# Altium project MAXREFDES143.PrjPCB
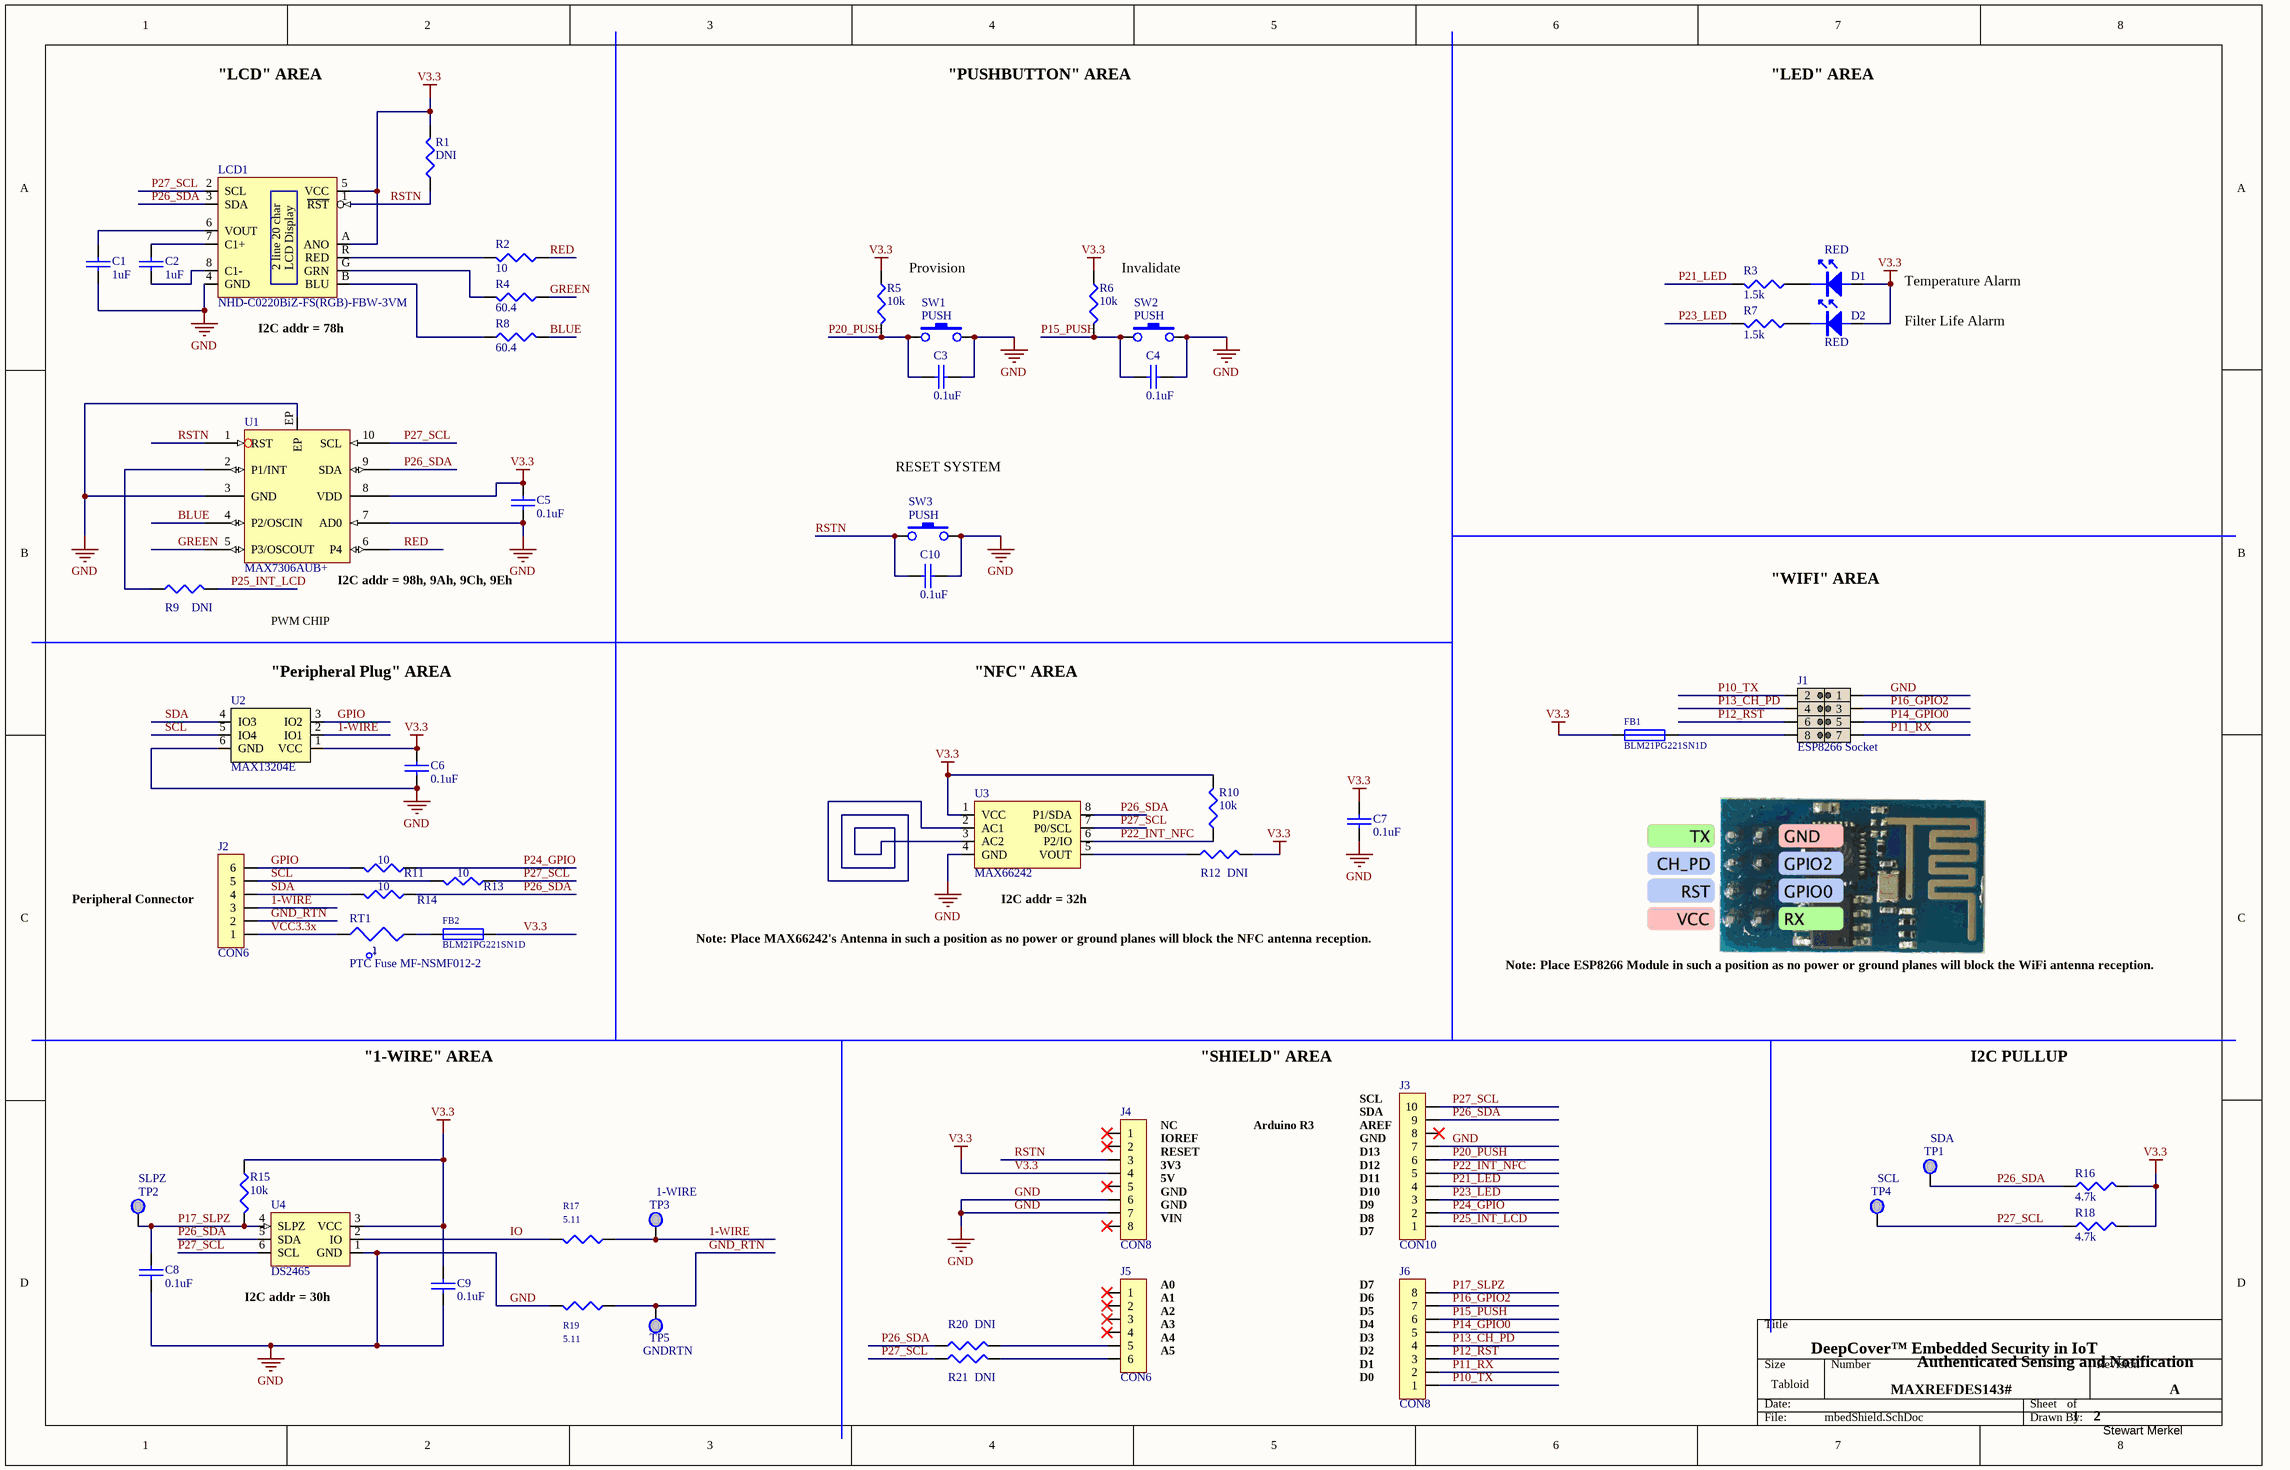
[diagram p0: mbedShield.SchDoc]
2 sheets, 65 parts. Net scope: flat (ports and power ports of the same name join across sheets).
Board file: MAXREFDES143.PcbDoc
Sheets:
  mbedShield.SchDoc
  ProtectedSensorNode.SchDoc

## Sheet mbedShield.SchDoc
size Tabloid; SheetNumber: 1; SheetTotal: 1; PageSetup: Record=PageOptions|CenterHorizontal=True|CenterVertical=True|PrintScale=0.95|XCorrection=1.00|YCorrection=1.00|PrintKind=1|BorderSize=5000000|LeftOffset=0|BottomOffset=0|Orientation=2|PaperLength=4318|PaperWidth=2794|Scale=100|PaperSource=7|PrintQuality=600|MediaType=1|DitherType=10|PaperKind=11x17|PrintScaleMode=1

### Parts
C1  1uF  [CAP0603-3D]
C2  1uF  [CAP0603-3D]
C3  0.1uF  [CAP0603-3D]
C4  0.1uF  [CAP0603-3D]
C5  0.1uF  [CAP0603-3D]
C6  0.1uF  [CAP0603-3D]
C7  0.1uF  [CAP0603-3D]
C8  0.1uF  [CAP0603-3D]
C9  0.1uF  [CAP0603-3D]
C10  0.1uF  [CAP0603-3D]
D1  RED  [0603LED-3DRED]
D2  RED  [0603LED-3DRED]
FB1  BLM21PG221SN1D  [0805FB-3D]
FB2  BLM21PG221SN1D  [0805FB-3D]
J1  ESP8266 Socket  [DIH4X2]
J2  CON6  [SIP6]
J3  CON10  [SIP10-FEM-3D]
J4  CON8  [SIP8-FEM-3D]
J5  CON6  [SIP6-FEM-3D]
J6  CON8  [SIP8-FEM-3D]
LCD1  NHD-C0220BiZ-FS(RGB)-FBW-3VM  [NHD RGB LCD 1]
R1  DNI  [0603-3D]  (no BOM)
R2  10  [0603-3D]
R3  1.5k  [0603-3D]
R4  60.4  [0603-3D]
R5  10k  [0603-3D]
R6  10k  [0603-3D]
R7  1.5k  [0603-3D]
R8  60.4  [0603-3D]
R9  DNI  [0603-3D]  (no BOM)
R10  10k  [0603-3D]
R11  10  [0603-3D]
R12  DNI  [0603-3D]  (no BOM)
R13  10  [0603-3D]
R14  10  [0603-3D]
R15  10k  [0603-3D]
R16  4.7k  [0603-3D]
R17  5.11  [0603-3D]
R18  4.7k  [0603-3D]
R19  5.11  [0603-3D]
R20  DNI  [0603-3D]  (no BOM)
R21  DNI  [0603-3D]  (no BOM)
RT1  PTC Fuse MF-NSMF012-2  [1206POLYFUSE-3D]
SW1  PUSH  [RESET11-3D]
SW2  PUSH  [RESET11-3D]
SW3  PUSH  [RESET11-3D]
TP1  SDA  [TP]  (no BOM)
TP2  SLPZ  [TP]  (no BOM)
TP3  1-WIRE  [TP]  (no BOM)
TP4  SCL  [TP]  (no BOM)
TP5  GNDRTN  [TP]  (no BOM)
U1  MAX7306AUB+  [uMax10]
U2  MAX13204E  [TDFN6 2MM .65]
U3  MAX66242  [SO-8-3D]
U4  DS2465  [SOP6]

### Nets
GND: C1.2 C3.2 C4.2 C5.2 C6.2 C7.2 C8.1 C9.1 C10.2 J1.1 J3.7 J4.6 J4.7 LCD1.4(GND) R19.2 SW1.2 SW2.2 SW3.2 U1.3(GND) U1.7(AD0) U1.EP U2.6(GND) U3.4(GND) U4.1(GND)
V3.3: C5.1 C6.1 C7.1 C9.2 D1.2 D2.2 FB1.1 FB2.2 J4.4 LCD1.5(VCC) LCD1.A(ANO) R1.2 R5.2 R6.2 R10.2 R12.2 R15.2 R16.2 R18.2 U1.8(VDD) U2.1(VCC) U3.1(VCC) U4.3(VCC)
1-WIRE: J2.3 R17.1 TP3.1 U2.2(IO1)
BLUE: R8.2 U1.4(P2/OSCIN)
GND_RTN: J2.2 R19.1 TP5.1
GPIO: J2.6 R11.2 U2.3(IO2)
GREEN: R4.1 U1.5(P3/OSCOUT)
IO: R17.2 U4.2(IO)
P10_TX: J1.2 J6.1
P11_RX: J1.7 J6.2
P12_RST: J1.6 J6.3
P13_CH_PD: J1.4 J6.4
P14_GPIO0: J1.5 J6.5
P15_PUSH: C4.1 J6.6 R6.1 SW2.1
P16_GPIO2: J1.3 J6.7
P17_SLPZ: C8.2 J6.8 R15.1 TP2.1 U4.4(SLPZ)
P20_PUSH: C3.1 J3.6 R5.1 SW1.1
P21_LED: J3.4 R3.1
P22_INT_NFC: J3.5 R10.1 U3.6(P2/IO)
P23_LED: J3.3 R7.1
P24_GPIO: J3.2 R11.1
P25_INT_LCD: J3.1 R9.2
P26_SDA: J3.9 LCD1.3(SDA) R14.1 R16.1 R20.1 TP1.1 U1.9(SDA) U3.8(P1/SDA) U4.5(SDA)
P27_SCL: J3.10 LCD1.2(SCL) R13.1 R18.1 R21.1 TP4.1 U1.10(SCL) U3.7(P0/SCL) U4.6(SCL)
RED: R2.1 U1.6(P4)
RSTN: C10.1 J4.3 LCD1.1(~{RST}) R1.1 SW3.1 U1.1(RST)
SCL: J2.5 R13.2 U2.5(IO4)
SDA: J2.4 R14.2 U2.4(IO3)
VCC3.3x: J2.1 RT1.2
NetC1_1: C1.1 LCD1.6(VOUT)
NetC2_1: C2.1 LCD1.7(C1+)
NetC2_2: C2.2 LCD1.8(C1-)
NetD1_1: D1.1 R3.2
NetD2_1: D2.1 R7.2
NetFB1_2: FB1.2 J1.8
NetFB2_1: FB2.1 RT1.1
NetJ5_5: J5.5 R20.2
NetJ5_6: J5.6 R21.2
NetLCD1_B: LCD1.B(BLU) R8.1
NetLCD1_G: LCD1.G(GRN) R4.2
NetLCD1_R: LCD1.R(RED) R2.2
NetR9_1: R9.1 U1.2(P1/INT)
NetR12_1: R12.1 U3.5(VOUT)
NetU3_2: U3.2(AC1) U3.3(AC2)

Not connected (* = marked no-connect by the designer): J3 8*; J4 1* 2* 5* 8*; J5 1* 2* 3* 4*

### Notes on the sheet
- "LCD" AREA
- "PUSHBUTTON" AREA
- "LED" AREA
- (near R5) Provision
- (near R6) Invalidate
- Temperature Alarm
- (near LCD1) I2C addr = 78h
- Filter Life Alarm
- RESET SYSTEM
- PWM CHIP
- (near U1) I2C addr = 98h, 9Ah, 9Ch, 9Eh
- "WIFI" AREA
- (near U2) "Peripheral Plug" AREA
- "NFC" AREA
- (near J2) Peripheral Connector
- Note: Place MAX66242's Antenna in such a position as no power or ground planes will block the NFC antenna reception.
- (near U3) I2C addr = 32h
- Note: Place ESP8266 Module in such a position as no power or ground planes will block the WiFi antenna reception.
- "1-WIRE" AREA
- "SHIELD" AREA
- I2C PULLUP
- (near J4) NC
- (near J4) IOREF
- (near J4) RESET
- Arduino R3
- (near J3) SCL
- (near J3) SDA
- (near J3) AREF
- (near J3) D13
- (near J3) GND
- (near J4) 3V3
- (near J4) 5V
- (near J4) GND
- (near J4) VIN
- (near J3) D12
- (near J3) D11
- (near J3) D10
- D9
- D8
- (near J5) A0
- D7
- (near U4) I2C addr = 30h
- (near J5) A1
- (near J5) A2
- (near J5) A3
- (near J5) A4
- (near J5) A5
- D5
- D4
- D3
- D2
- D6
- DeepCover™ Embedded Security in IoT
- D1
- D0
- MAXREFDES143#
- Authenticated Sensing and Notification
- 1
- 2
- A
- Stewart Merkel

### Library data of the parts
C1 C2 = CAP: CAP CER 1UF 10V 10% X7R 0603; Manufacture Name: Taiyo Yuden; Part Number: LMK107B7105KA-T; Vendor Part Number: 587-1242-2-ND; Vendor: Digikey
C3-C5 C10 = CAP: CAP CER 0.1UF 16V 10% X7R 0603; Manufacture Name: Samsung Electro-Mechanics America, Inc; Part Number: CL10B104KO8NNNC; Vendor Part Number: 1276-1005-2-ND; Vendor: Digikey
C6-C9 = CAP: CAP CER 0.1UF 16V 10% X7R 0603; Manufacture Name: Samsung Electro-Mechanics America, Inc; Part Number: CL10B104KO8NNNC; Internal Part Number: EC2256
D1 D2 = LED: LED RED RECT CLEAR 0603; Manufacture Name: Lite-On Inc; Part Number: LTST-C193KRKT-5A; Vendor Part Number: 160-1830-1-ND; Vendor: Digikey
FB1 FB2 = FUSE1: Ferrite Chip; Manufacture Name: Murata Electronics North America; Vendor Part Number: 490-1054-1-ND; Vendor: Digikey
J1 = JUMPBLOCK 4: 8 Position Header Socket 0.100" (2.54mm) Through Hole; Manufacture Name: Sullins Connector Solutions; Part Number: PPTC042LFBN-RC; Vendor Part Number: S7072-ND; Vendor: Digikey
J2 = CON6: 6 Position Header Socket 0.100" (2.54mm) Through Hole, Right Angle; Manufacture Name: Sullins Connector Solutions; Part Number: PPPC061LGBN-RC; Vendor Part Number: S5481-ND; Vendor: Digikey
J3 = CON10: 10 Position Header 0.100" (2.54mm) Through Hole; Manufacture Name: Sullins Connector Solutions; Part Number: PREC040SAAN-RC; Vendor Part Number: S1012EC-40-ND; Vendor: Digikey
J4 J6 = CON8: 8 Position Header 0.100" (2.54mm) Through Hole; Manufacture Name: Sullins Connector Solutions; Part Number: PREC040SAAN-RC; Vendor Part Number: S1012EC-40-ND; Vendor: Digikey
J5 = CON6: 6 Position Header 0.100" (2.54mm) Through Hole; Manufacture Name: Sullins Connector Solutions; Part Number: PREC040SAAN-RC; Vendor Part Number: S1012EC-40-ND; Vendor: Digikey
LCD1 = NHD C0220BiZ-FS(RGB)-FBW-3VM: LCD DISPLAY RGB LED BKLT 20 X 2; Manufacture Name: Newhaven Display Intl; Vendor Part Number: NHD-C0220BIZ-FS(RGB)-FBW-3VM-ND; Vendor: Digikey
R1 = RESISTOR: RES 10K OHM 1/10W 1% 0603 SMD; Manufacture Name: Panasonic Electronic Components; Part Number: ERJ-3EKF1002V; Vendor Part Number: P10.0KHTR-ND; Vendor: Digikey
R2 R11 R13 R14 = RESISTOR: RES 10 OHM 1/10W 1% 0603 SMD; Manufacture Name: Panasonic Electronic Components; Part Number: ERJ-3EKF10R0V; Vendor Part Number: P10.0HTR-ND; Vendor: Digikey
R3 R7 = RESISTOR: RES SMD 1.5K OHM 1% 1/10W 0603; Manufacture Name: Panasonic Electronic Components; Part Number: ERJ-3EKF1501V; Vendor Part Number: P1.50KHTR-ND; Vendor: Digikey
R4 = RESISTOR: Manufacture Name: Panasonic Electronic Components; Part Number: ERJ-3EKF60R4V; Vendor Part Number: P60.4HCT-ND; Vendor: Digikey
R5 R6 R10 R15 = RESISTOR: RES SMD 10K OHM 1% 1/10W 0603; Manufacture Name: Panasonic Electronic Components; Part Number: ERJ-3EKF1002V; Vendor Part Number: P10.0KHTR-ND; Vendor: Digikey
R8 = RESISTOR: RES 60.4 OHM 1/10W 1% 0603 SMD; Manufacture Name: Panasonic Electronic Components; Part Number: ERJ-3EKF60R4V; Vendor Part Number: P60.4HCT-ND; Vendor: Digikey
R9 R12 R20 R21 = RESISTOR
R16 R18 = RESISTOR: RES SMD 4.7K OHM 1% 1/10W 0603; Manufacture Name: Panasonic Electronic Components; Part Number: ERJ-3EKF4701V; Vendor Part Number: P4.70KHCT-ND; Vendor: Digikey
R17 R19 = RESISTOR: RES SMD 5.11 OHM 1% 1/10W 0603; Manufacture Name: Yageo; Part Number: RC0603FR-075R11L; Vendor Part Number: 311-5.11HRCT-ND; Vendor: Digikey
RT1 = THERMISTOR: PTC Fuse 1206; Manufacture Name: Bourns Inc.; Internal Part Number: EH1032
SW1-SW3 = SW-PB: SWITCH TACTILE SPST-NO 0.05A 32V; Manufacture Name: C&K Components; Part Number: KSR221GLFS; Vendor Part Number: 401-1703-1-ND; Notes: IP-50 Dust only; Vendor: Digikey
TP1-TP5 = TP: Test Point; Internal Part Number: EH0400; Manufacture Name: Keystone Electronics; Part Number: 5011
U1 = MAX7306: SMBus/I²C Interfaced 4-Port, Level-Translating GPIOs and LED Drivers; Manufacture Name: Maxim Integrated
U2 = MAX13204: 4 Channel +/- 30kv ESD Protector; Manufacture Name: Maxim Integrated; Part Number: MAX13204EALT+
U3 = MAX2XXX: DeepCover Secure Authenticator with ISO 15693, I²C, SHA-256, and 4Kb User EEPROM; Manufacture Name: Maxim Integrated; Part Number: MAX66242ISA-A+
U4 = DSKCP1: DeepCover Secure Authenticator with SHA-256 Coprocessor and 1-Wire Master Function; Internal Part Number: 90-2465P+000; Manufacture Name: Maxim Integrated; Part Number: DS2465P+

## Sheet ProtectedSensorNode.SchDoc
size Tabloid
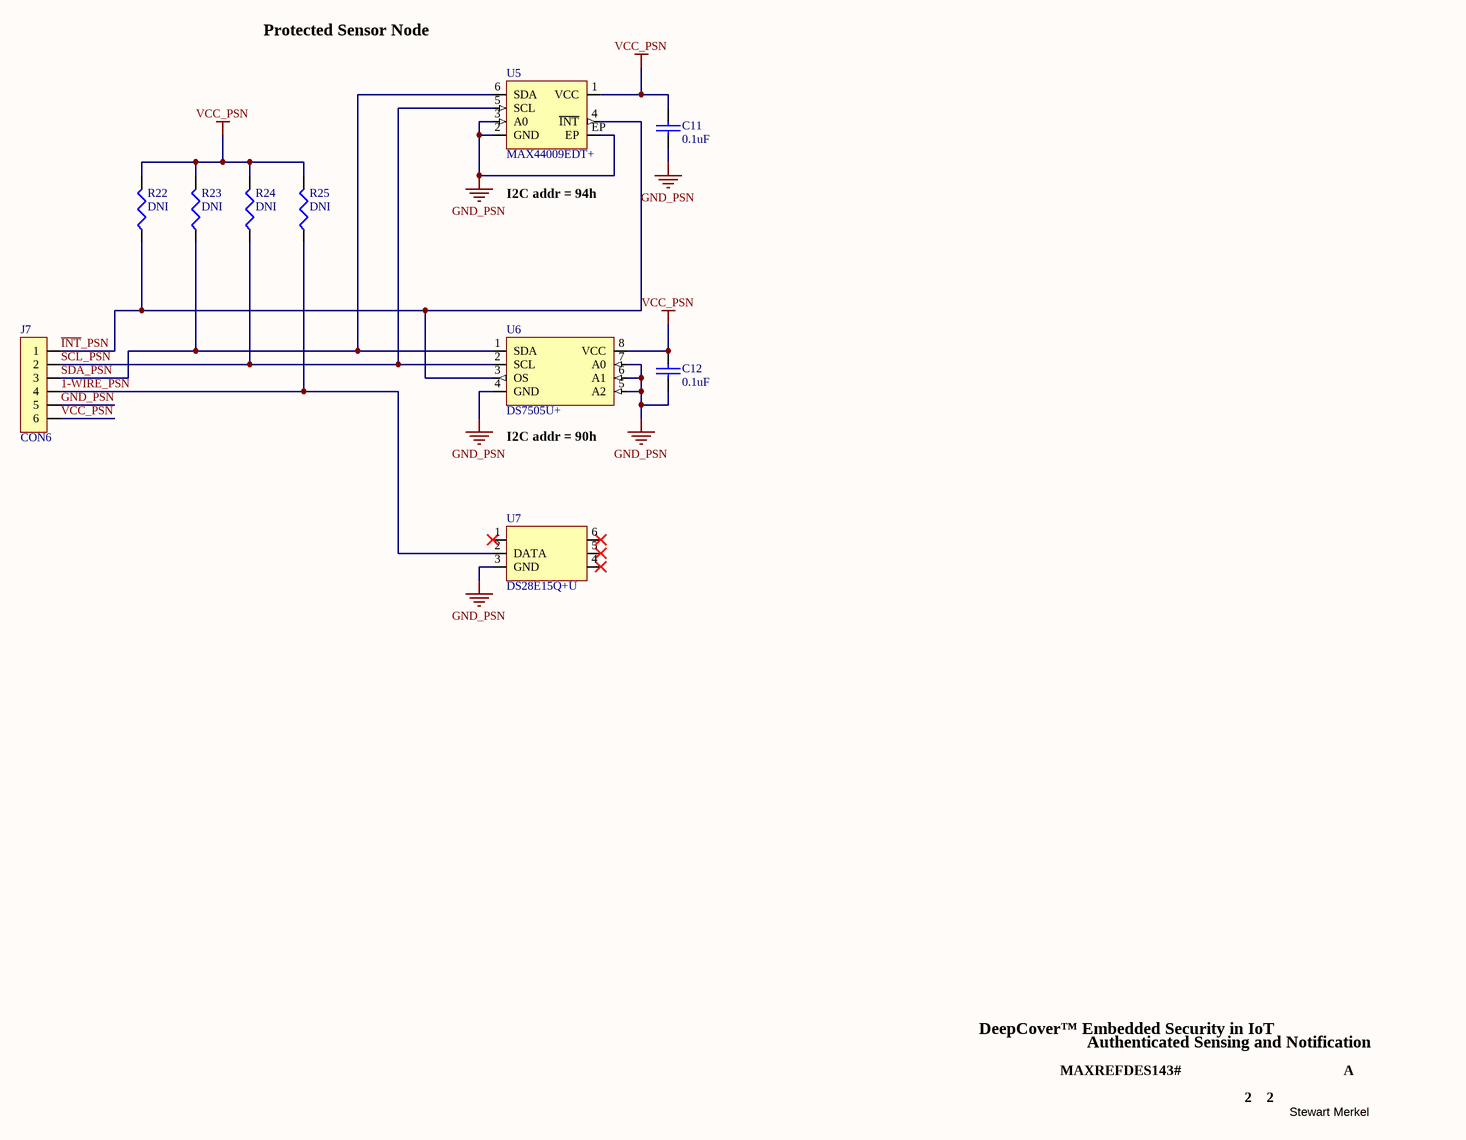
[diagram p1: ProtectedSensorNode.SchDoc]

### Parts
C11  0.1uF  [CAP0603-3D]
C12  0.1uF  [CAP0603-3D]
J7  CON6  [SIP6-HEADER-RA-3D]
R22  DNI  [0603-3D]  (no BOM)
R23  DNI  [0603-3D]  (no BOM)
R24  DNI  [0603-3D]  (no BOM)
R25  DNI  [0603-3D]  (no BOM)
U5  MAX44009EDT+  [TDFN6 .65P 2x2MM]
U6  DS7505U+  [UMAX8]
U7  DS28E15Q+U  [TDFN6 3MM .95]

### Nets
GND_PSN: C11.2 C12.2 J7.5 U5.2(GND) U5.3(A0) U5.EP U6.4(GND) U6.5(A2) U6.6(A1) U6.7(A0) U7.3(GND)
VCC_PSN: C11.1 C12.1 J7.6 R22.2 R23.2 R24.2 R25.2 U5.1(VCC) U6.8(VCC)
1-WIRE_PSN: J7.4 R25.1 U7.2(DATA)
~{INT}_PSN: J7.1 R22.1 U5.4(~{INT}) U6.3(OS)
SCL_PSN: J7.2 R24.1 U5.5(SCL) U6.2(SCL)
SDA_PSN: J7.3 R23.1 U5.6(SDA) U6.1(SDA)

Not connected (* = marked no-connect by the designer): U7 1* 4* 5* 6*

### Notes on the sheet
- Protected Sensor Node
- (near U5) I2C addr = 94h
- (near U6) I2C addr = 90h
- DeepCover™ Embedded Security in IoT
- MAXREFDES143#
- Authenticated Sensing and Notification
- 2
- A
- Stewart Merkel

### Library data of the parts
C11 C12 = CAP: as C3 on sheet mbedShield
J7 = CON6: 6 Position Header 0.100" (2.54mm) Through Hole, Right Angle; Manufacture Name: Sullins Connector Solutions; Part Number: PRPC040SBAN-M71RC; Vendor Part Number: S1111EC-40-ND; Vendor: Digikey
R22-R25 = RESISTOR
U5 = MAX44009: Ambient Light Sensor with ADC; Manufacture Name: Maxim Integrated
U6 = DS75: Digital Thermometer and Thermostat; Manufacture Name: Maxim Integrated
U7 = DS28E15 TDFN: DeepCover Secure Authenticator with 1-Wire SHA-256 and 512-Bit User EEPROM; Manufacture Name: Maxim Integrated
